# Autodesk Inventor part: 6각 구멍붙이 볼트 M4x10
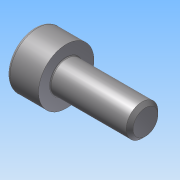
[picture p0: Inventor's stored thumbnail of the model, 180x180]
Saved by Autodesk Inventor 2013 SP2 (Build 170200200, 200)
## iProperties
Created: 2025-08
Part Number: 6각 구멍붙이 볼트 M4x10
Material: Generic
Document SubType Name: Modeling
Designer: i
Density: 1 g/cm^3
Author: i
변환 표준: STEP AP214IS
전처리기: Build: 200, Release: 2013 SP2 Update 6 - Date: Thu 07/17/2014
전송 단위: 밀리미터
불확실성: 0.01
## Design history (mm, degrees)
node "6각 구멍붙이 볼트 M4x101"
body "Solid1"
node "기준1"
